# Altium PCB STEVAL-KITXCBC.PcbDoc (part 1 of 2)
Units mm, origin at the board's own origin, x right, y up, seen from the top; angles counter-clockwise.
Board outline 110 x 100 mm, 4 copper layers (Top Layer, Ground Layer, Power Layer, Bottom Layer), stack 1.572 mm thick; 141 components, 96 nets, 501 pads, 315 vias.
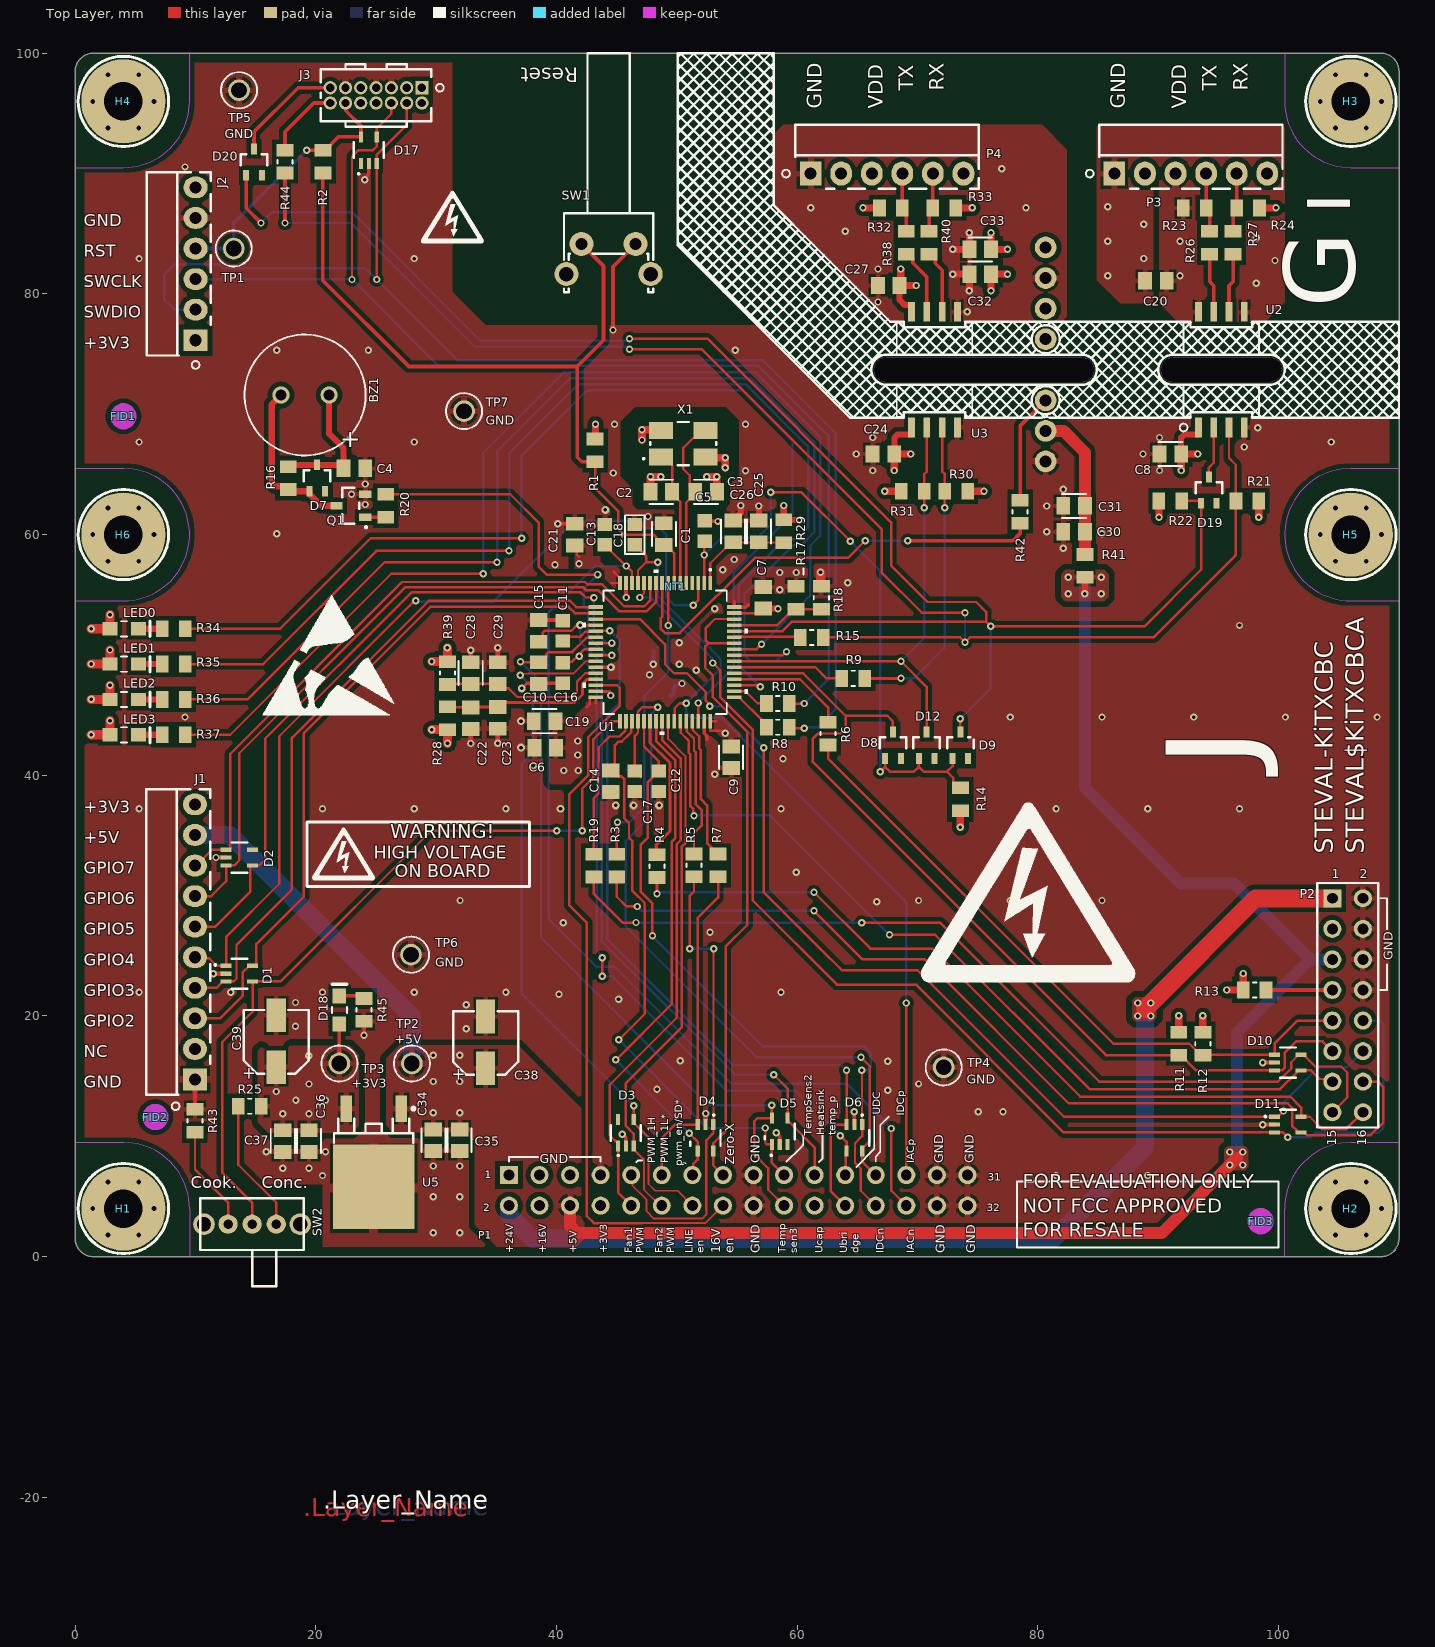
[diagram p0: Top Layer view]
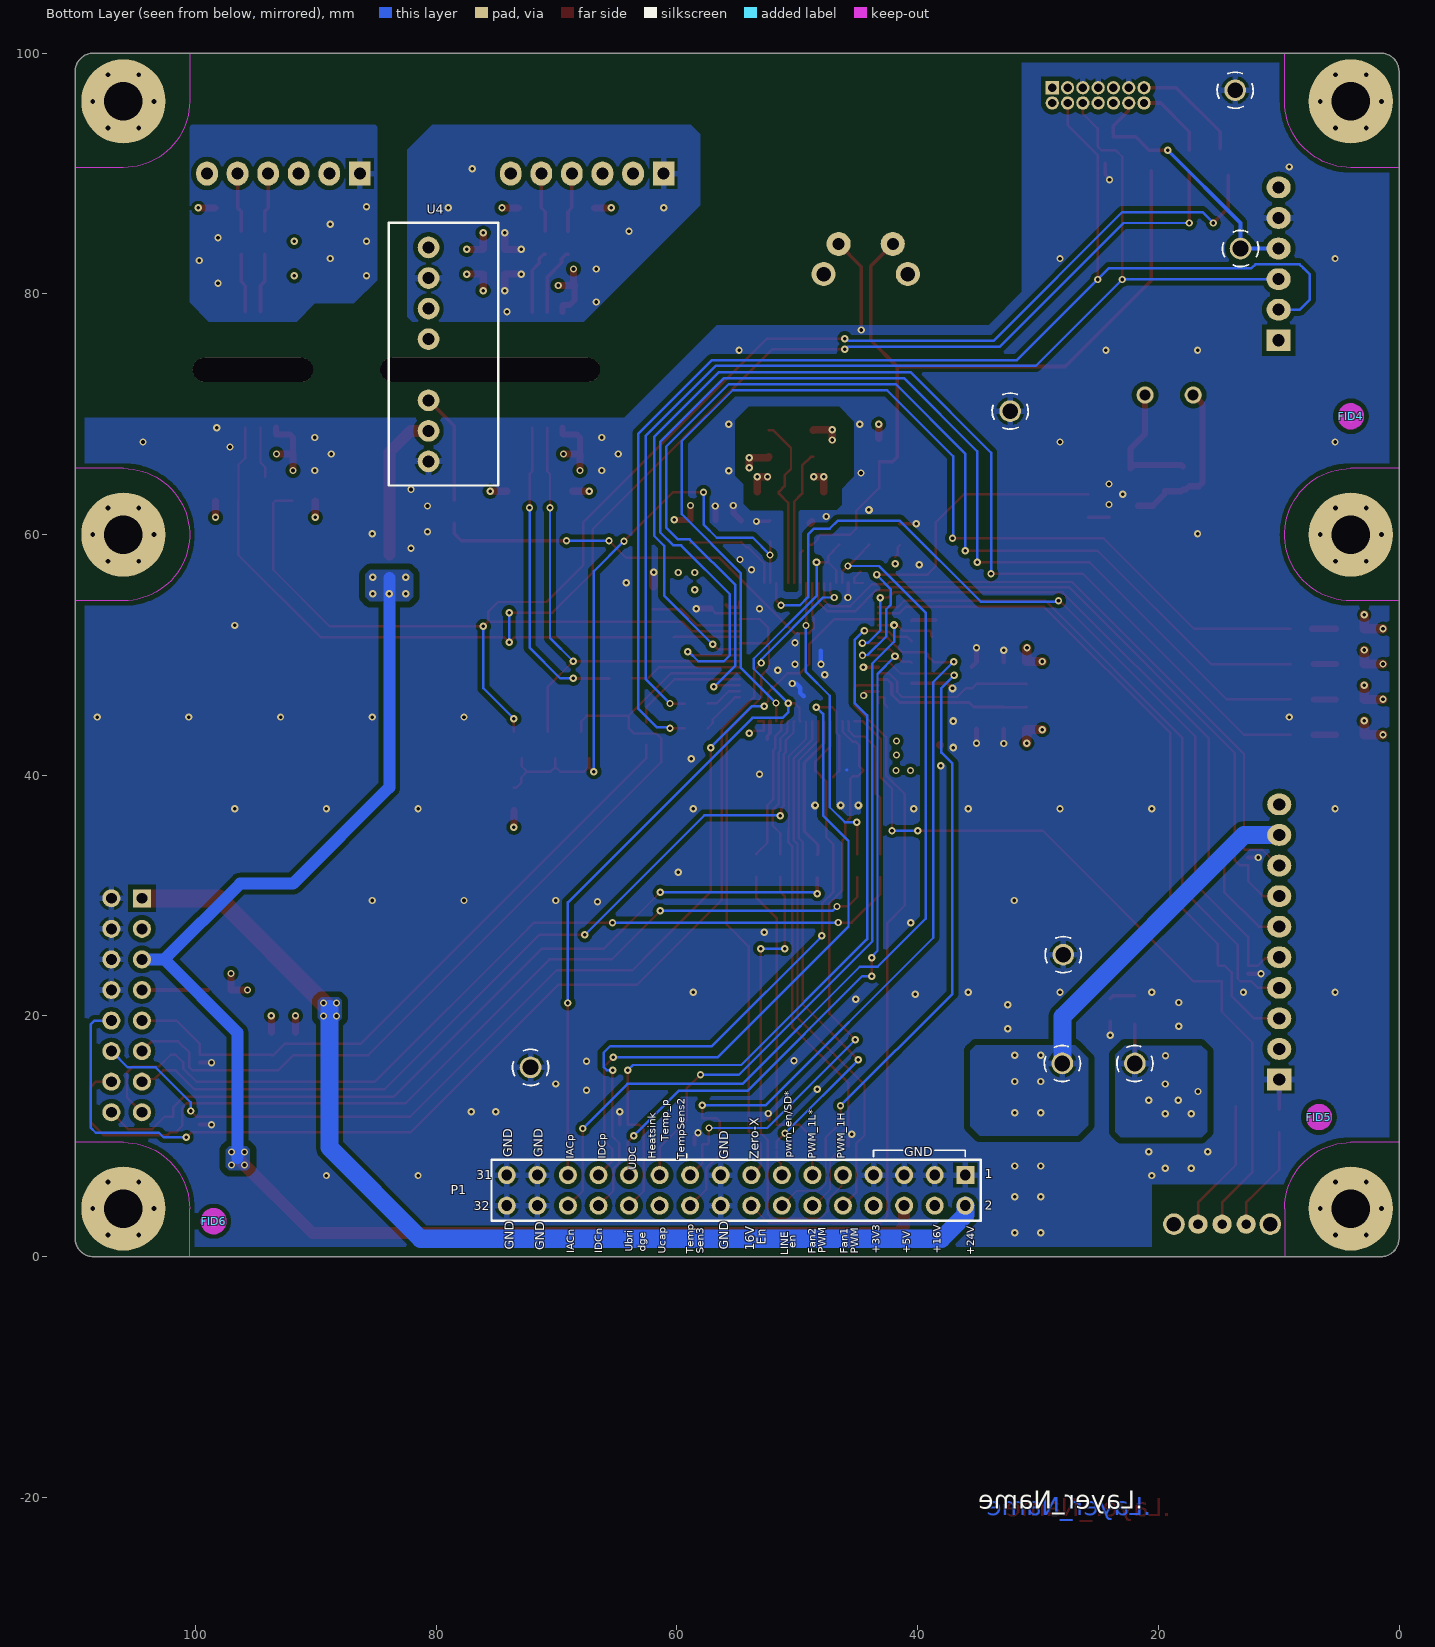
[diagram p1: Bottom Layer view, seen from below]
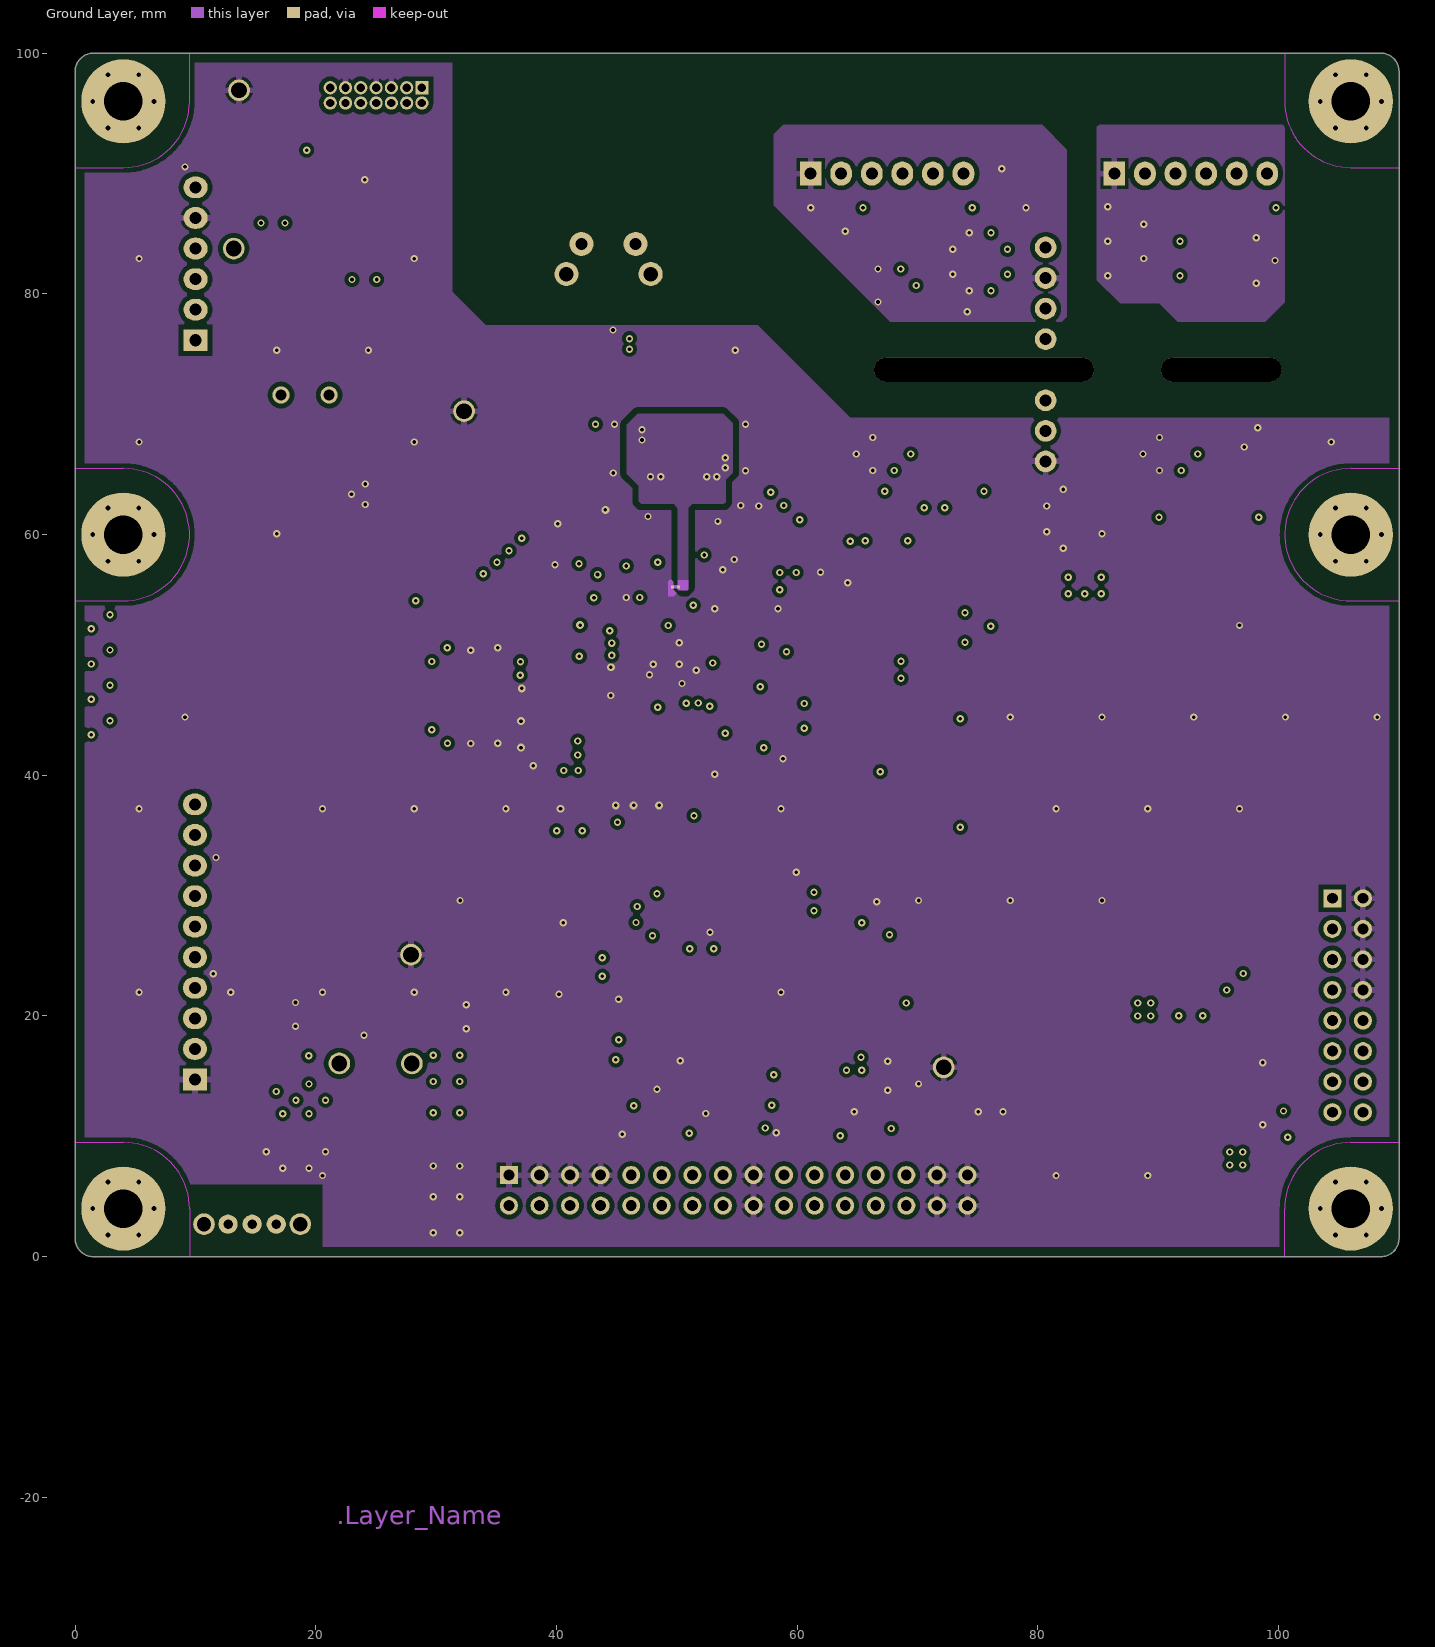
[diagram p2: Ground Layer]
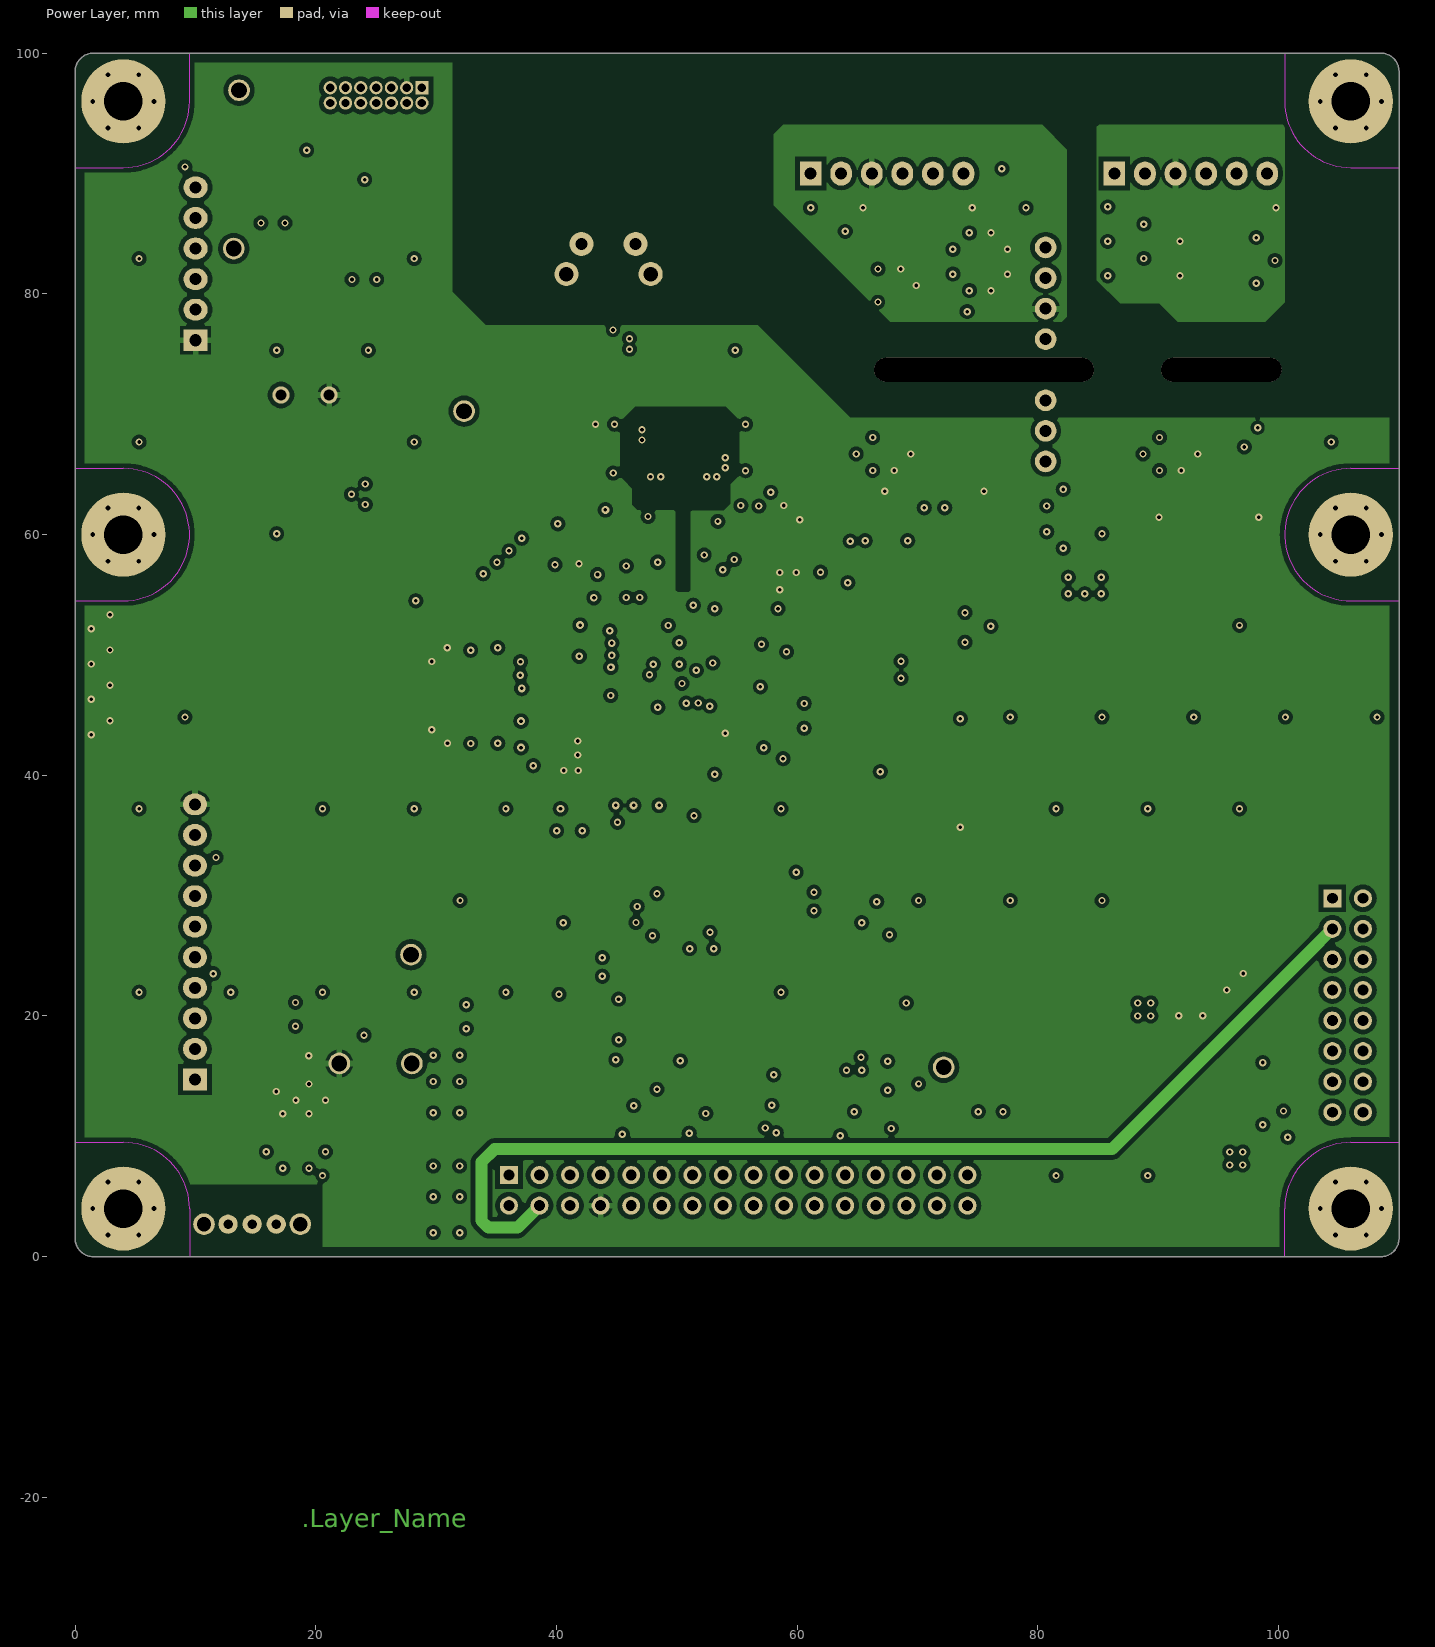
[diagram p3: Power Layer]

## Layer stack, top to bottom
Top Solder: solder mask 0.0127, Solder Resist, Dk 3.5
Top Layer: signal copper 0.0356
Dielectric1: prepreg 0.36, FR-4 High TG, Dk 4.2
Ground Layer: signal copper 0.0356
Dielectric 2: core 0.71, FR-4 High TG, Dk 4.2
Power Layer: signal copper 0.0356
Dielectric 3: prepreg 0.36, FR-4 High TG, Dk 4.2
Bottom Layer: signal copper 0.0356
Bottom Solder: solder mask 0.0127, Solder Resist, Dk 3.5

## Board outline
1.5,0 cw(c1.5,1.5) 0,1.5 0,98.5 cw(c1.5,98.5) 1.5,100 108.5,100 cw(c108.5,98.5) 110,98.5 110,1.5 cw(c108.5,1.5) 108.5,0

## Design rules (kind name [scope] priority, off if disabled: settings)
AcuteAngle [All] p1: minimum=4.50000000000000E+0001 checktracksonly=FALSE
AssemblyTestPointUsage [All] p1: valid=2
BoardOutlineClearance BoardOutlineClearance_MountingHoles [OnCopper and InComponentClass('Mounting Holes')] p1: gap=1.016 ignorepadtopadclearanceinfootprint=FALSE
BoardOutlineClearance BoardOutlineClearance_Poly [OnCopper and IsPoly] p2: gap=0.8 ignorepadtopadclearanceinfootprint=FALSE
BoardOutlineClearance [OnCopper and Not InComponentClass('Logo') and not InComponentClass('FiducialMark') and not InRegion(1000,500,4000,800) and not InPoly] p3: gap=0.737 ignorepadtopadclearanceinfootprint=FALSE except(0.635: SMDPad-OutlineEdge THPad-OutlineEdge)
Clearance Clearance_Keepouts [((IsTrack Or IsArc) And Not InPoly) And IsFree and IsKeepOut vs ((IsTrack Or IsArc) And Not InPoly) And IsFree and IsKeepOut] p1: gap=0 ignorepadtopadclearanceinfootprint=FALSE
Clearance Clearance_Poly [InPolygon] p2: gap=0.254 ignorepadtopadclearanceinfootprint=TRUE except(0.305: Via-Poly; 0.381: Arc-Poly Track-Poly SMDPad-Poly THPad-Poly Fill-Poly; 0.508: Poly-Poly)
Clearance Clearance_FiducialMark [IsKeepOut and InComponentClass('FiducialMark') vs IsPad and InComponentClass('FiducialMark')] p3: gap=0 ignorepadtopadclearanceinfootprint=FALSE
Clearance [All] p4: gap=0.229 ignorepadtopadclearanceinfootprint=TRUE except(0: Arc-SMDPad; 0.193: Track-SMDPad SMDPad-SMDPad; 0.508: Poly-Poly)
ComponentClearance ComponentClearance_MountingHoles_FiducialMarks [InComponentClass('Mounting Holes') vs InComponentClass('FiducialMark')] p1: gap=1.27 collisioncheckmode=3 verticalgap=0.254 showdistances=FALSE
ComponentClearance ComponentClearance_Shunt [InComponentClass('Header') vs InComponentClass('Shunt')] p2: gap=0 collisioncheckmode=3 verticalgap=0 showdistances=FALSE
ComponentClearance ComponentClearance_Logo [InComponentClass('Logo')] p3: gap=1.016 collisioncheckmode=3 verticalgap=0.254 showdistances=FALSE
ComponentClearance ComponentClearance_ScrewToNut [(HasFootprint('NY PMS 440 0025 PH')) vs (HasFootprint('Keystone_1902C'))] p4: gap=0.127 collisioncheckmode=3 verticalgap=0.254 showdistances=FALSE
ComponentClearance ComponentClearance_MountingHoles [InComponentClass('Mounting Holes')] p5: gap=6.35 collisioncheckmode=3 verticalgap=2540 showdistances=FALSE
ComponentClearance ComponentClearance_SmallPassives [HasFootprint('0201*') or HasFootprint('0402*') or HasFootprint('0508') or HasFootprint('0603*') or HasFootprint('0612') or HasFootprint('0805*') or HasFootprint('0815*') or HasFootprint('0830*') or HasFootprint('1206*') or HasFootprint('1210*') or HasFootprint('1808*') or HasFootprint('1812*') or HasFootprint('1825*') or HasFootprint('2010*') or HasFootprint('2220*') or HasFootprint('2225*') or HasFootprint('2512*') or HasFootprint('2728*') or HasFootprint('3518*') vs HasFootprint('0201*') or HasFootprint('0402*') or HasFootprint('0508') or HasFootprint('0603*') or HasFootprint('0612') or HasFootprint('0805*') or HasFootprint('0815*') or HasFootprint('0830*') or HasFootprint('1206*') or HasFootprint('1210*') or HasFootprint('1808*') or HasFootprint('1812*') or HasFootprint('1825*') or HasFootprint('2010*') or HasFootprint('2220*') or HasFootprint('2225*') or HasFootprint('2512*') or HasFootprint('2728*') or HasFootprint('3518*')] p6: gap=0.38 collisioncheckmode=3 verticalgap=0.254 showdistances=FALSE
ComponentClearance ComponentClearance_THtoSMT [IsThruComponent vs IsSMTComponent] p7: gap=0.762 collisioncheckmode=3 verticalgap=0.635 showdistances=FALSE
ComponentClearance ComponentClearance_THtoTH [IsThruComponent vs IsThruComponent] p8: gap=0.762 collisioncheckmode=3 verticalgap=0.635 showdistances=FALSE
ComponentClearance [All] p9: gap=0.635 collisioncheckmode=3 verticalgap=0.254 showdistances=FALSE
DiffPairsRouting [All] p1: maxlimit=2.54 minlimit=0.254 mostfreqgap=0.254 toplayer_minwidth=0.381 toplayer_maxwidth=0.381 toplayer_prefwidth=0.381 midlayer1_minwidth=0.381 midlayer1_maxwidth=0.381 midlayer1_prefwidth=0.381 midlayer2_minwidth=0.381 midlayer2_maxwidth=0.381 midlayer2_prefwidth=0.381 bottomlayer_minwidth=0.381 bottomlayer_maxwidth=0.381 bottomlayer_prefwidth=0.381 maxuncoupledlength=25.4
FabricationTestPointUsage TestPointUsage [All] p1: valid=2 allowmultiple=FALSE
FabricationTestpoint Testpoint [All] p1: side=3 testpointundercomponent=TRUE minsize=1.016 maxsize=2.54 preferedsize=1.524 minholesize=0 maxholesize=1.016 preferedholesize=0.813 testpointgrid=0.025 allowsidetop=TRUE allowsidebottom=TRUE usegrid=TRUE gridtolerance=0
FanoutControl Fanout_LCC [IsLCC] p1: bgadir=Out bgaviamode=Centered fanoutstyle=Auto fanoutdirection=Alternating viagrid=0.025 // Fanout_LCC (Default Rule)
FanoutControl Fanout_BGA [IsBGA] p2: bgadir=Out bgaviamode=Centered fanoutstyle=Auto fanoutdirection=Alternating viagrid=0.025 // Fanout_BGA (Default Rule)
FanoutControl Fanout_Default [All] p4: bgadir=Out bgaviamode=Centered fanoutstyle=Auto fanoutdirection=Alternating viagrid=0.025 // Fanout_Default (Default Rule)
FanoutControl Fanout_Small [(CompPinCount < 5)] p5: bgadir=Out bgaviamode=Centered fanoutstyle=Auto fanoutdirection=OutThenIn viagrid=0.025 // Fanout_Small (Default Rule)
HoleSize [All] p1: absolutevalues=TRUE maxlimit=10 minlimit=0.2 maxpercent=80.000 minpercent=20.000
HoleToHoleClearance [All] p1: gap=0.2 allowstackedmicrovias=TRUE
MinimumAnnularRing MinimumAnnularRing_ThermalPadVias [IsVia and InAnyComponent] p1: minimumring=0.15
MinimumAnnularRing [All] p2: minimumring=0.127
MinimumSolderMaskSliver MinimumSolderMaskSliver_Logo [InComponentClass('Logo') vs InComponentClass('Logo')] p1: minsoldermaskwidth=0.018
MinimumSolderMaskSliver [All] p2: minsoldermaskwidth=0.01
PlaneConnect [All] p1: planeconnectstyle=Relief reliefexpansion=0.254 reliefentries=4 reliefconductorwidth=0.254 reliefairgap=0.254
PolygonConnect [All] p1: thpad.connectstyle=Relief thpad.reliefconductorwidth=0.508 thpad.reliefentries=4 thpad.polygonreliefangle="90 Angle" thpad.airgapwidth=0.254 smdpad.connectstyle=Relief smdpad.reliefconductorwidth=0.4 smdpad.reliefentries=4 smdpad.polygonreliefangle="90 Angle" smdpad.airgapwidth=0.2 via.connectstyle=Direct via.reliefconductorwidth=0.254 via.reliefentries=4 via.polygonreliefangle="90 Angle" via.airgapwidth=0.254
RoutingVias ThermalPadVias [IsVia and InAnyComponent] p1: holewidth=0.2 width=0.5 viastyle="Through Hole" minholewidth=0.2 minwidth=0.5 maxholewidth=0.33 maxwidth=0.6
RoutingVias [All] p2: holewidth=0.305 width=0.61 viastyle="Through Hole" minholewidth=0.3 minwidth=0.6 maxholewidth=0.31 maxwidth=0.62
SilkToBoardRegionClearance [Not ((IsComment or IsDesignator) And (Hide <> 'False')) and not InRegion(1000,500,4000,800)] p1:
SilkToSilkClearance SilkToSilkClearance_Pb-FreeLogo [(HasFootprint('Pb-Free_Overlay_Medium') OR HasFootprint('Pb-Free_Overlay_Small')) vs (HasFootprint('Pb-Free_Overlay_Medium') OR HasFootprint('Pb-Free_Overlay_Small'))] p1: silktosilkclearance=0
SilkToSilkClearance [All] p2: silktosilkclearance=0.013
SilkToSolderMaskClearance SilkToComponentPadClearance [(IsPad or IsFill or IsRegion) and InAnycomponent] p1: minsilkscreentomaskgap=0.01 clearancetoexposedcopper=FALSE
SilkToSolderMaskClearance "Silk to Solder Mask Opening" [All] p2: minsilkscreentomaskgap=0 clearancetoexposedcopper=FALSE
SolderMaskExpansion [All] p1: expansion=0.1 istentingtop=FALSE
UnRoutedNet [All] p1: checkbadconnections=TRUE
Width [All] p1: maxlimit=2.54 minlimit=0.152 preferedwidth=0.254 minimp=50.000000 maximp=50.000000 favimp=50.000000 checkconnectedcopper=TRUE
13 further rules are at their usual default settings.

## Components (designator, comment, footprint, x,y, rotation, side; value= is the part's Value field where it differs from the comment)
BZ1 "ABI-050-RC" TR_MP-ABI-050-RC_MTC 21.1,71.6 r180 top
C1 "100n" CC0805 48.916,60.046 r90 top locked
C2 "22p" CC0805 48.694,63.554 r0 top locked
C3 "22p" CC0805 52.425,63.554 r0 top locked
C4 "100n" CC0805 23.2,65.5 r0 top
C5 "1nF" CC0603 52.3,60.3 r90 top
C6 "10u" CC0805 39.05,42.3 r180 top
C7 "100n" CC0805 57.179,54.747 r270 top
C8 "100n" CC0805 91,66.7 r180 top locked
C9 "100n" CC0805 54.5,41.5 r270 top
C10 "100nF" CC0805 38.5,48.5 r270 top
C11 "1nF" CC0603 40.5,52 r90 top
C12 "1nF" CC0603 48.5,39.5 r270 top
C13 "1nF" CC0603 44,60 r90 top
C14 "100nF" CC0805 44.5,39.5 r270 top
C15 "100nF" CC0805 38.5,52 r90 top
C16 "1nF" CC0603 40.5,48.5 r270 top
C17 "1nF" CC0603 46.5,39.5 r270 top
C18 "1nF" CC0603 46.5,60 r90 top
C19 "100n" CC0805 39,44.5 r180 top
C20 "10n" CC0805 89.8,81.1 r180 top
C21 "100n" CC0805 41.5,60 r90 top
C22 "10u" CC0805 32.857,44.747 r270 top
C23 "100n" CC0805 35.107,44.762 r270 top
C24 "100n" CC0805 67.16,66.7 r180 top
C25 "10u" CC0805 56.808,60.271 r90 top locked
C26 "100n" CC0805 54.666,60.271 r90 top locked
C27 "10n" CC0805 67.6,80.7 r180 top
C28 "10u" CC0805 32.857,48.5 r90 top locked
C29 "100n" CC0805 35.107,48.5 r90 top
C30 "10u" CC0805 83,60.234 r180 top
C31 "100n" CC0805 83,62.384 r180 top
C32 "10u" CC0805 75.2,81.645 r180 top
C33 "100n" CC0805 75.2,83.7 r180 top
C34 "100n" CC0805 29.761,9.677 r270 top locked
C35 "10u" CC0805 31.941,9.677 r270 top locked
C36 "10u" CC0805 19.423,9.606 r270 top locked
C37 "100n" CC0805 17.252,9.606 r270 top locked
C38 "47u" "ELCAP SMD D5H5.8P1.5" 34.1,17.8 r0 top value=47uF
C39 "47u" "ELCAP SMD D5H5.8P1.5" 16.7,17.9 r0 top value=47uF
D1 "ESDALC6V1W5" SOT323_5 13.633,23.518 r270 top
D2 "ESDALC6V1W5" SOT323_5 13.633,33.164 r270 top
D3 "ESDALC6V1W5" SOT323_5 45.758,10.294 r0 top
D4 "ESDALC6V1W5" SOT323_5 52.371,9.87 r180 top
D5 "ESDALC6V1W5" SOT323_5 58.542,10.416 r0 top
D6 "ESDALC6V1W5" SOT323_5 64.742,9.87 r180 top
D7 "BAT54WFILM" SOT323 20.1,64.7 r0 top
D8 "BAT54WFILM" SOT323 67.95,42.5 r0 top
D9 "BAT54WFILM" SOT323 73.55,42.5 r0 top
D10 "ESDALC6V1W5" SOT323_5 100.762,16.129 r270 top
D11 "ESDALC6V1W5" SOT323_5 100.762,10.973 r270 top
D12 "BAT54WFILM" SOT323 70.75,42.5 r0 top
D17 "ESDALC6V1W5" SOT323_5 24.4,91.95 r0 top
D18 "KPT-2012SGC" LED_KPT-2012EC 21.948,20.5 r270 top
D19 "BAT54WFILM" SOT323 94.2,63.7 r0 top
D20 "BAT54WFILM" SOT323 14.854,90.956 r0 top
FID1 "Fiducial" Fiducial10-20 4,69.832 r0 top
FID2 "Fiducial" Fiducial10-20 6.655,11.6 r0 top
FID3 "Fiducial" Fiducial10-20 98.501,2.946 r0 top
FID4 "Fiducial" Fiducial10-20 4,69.832 r180 bottom
FID5 "Fiducial" Fiducial10-20 6.655,11.6 r180 bottom
FID6 "Fiducial" Fiducial10-20 98.501,2.946 r180 bottom
H1 "Hole" "HOLE_M3 - D8" 4,4 r0 top net-tie
H2 "Hole" "HOLE_M3 - D8" 106,4 r0 top net-tie
H3 "Hole" "HOLE_M3 - D8" 106,96 r0 top net-tie
H4 "Hole" "HOLE_M3 - D8" 4,96 r0 top net-tie
H5 "Hole" "HOLE_M3 - D8" 106,60 r0 top net-tie
H6 "Hole" "HOLE_M3 - D8" 4,60 r0 top net-tie
J1 "TSW-110-08-G-S-RA" "SIP10 - Male - RA" 9.95,26.15 r90 top
J2 "TSW-106-08-G-S-RA" "SIP6 - MALE - RA" 10,82.5 r90 top
J3 "FTSH-107-01-F-D-K" SAMTEC-FTSH-107-01-X-D-K 25,96.5 r180 top
LED0 "KPT-2012EC" LED_KPT-2012EC 4.069,52.178 r180 top
LED1 "KPT-2012SGC" LED_KPT-2012EC 4.069,49.242 r180 top
LED2 "APT2012YC" LED_KPT-2012EC 4.069,46.305 r180 top
LED3 "APTD2012LQBC/D" LED_KPT-2012EC 4.069,43.369 r180 top
NT1 "Net-Tie" Net-Tie_10mil 49.886,55.652 r180 top locked net-tie
P1 "SSW-116-01-G-D" HDR2X16 36.04,6.78 r0 bottom locked
P2 "TSW-108-07-G-D" HDR2X8 104.46,29.78 r270 top locked
P3 "TSW-106-08-G-S-RA" "SIP6 - MALE - RA" 92.7,90 r0 top
P4 "TSW-106-08-G-S-RA" "SIP6 - Male - RA" 67.46,90 r0 top
Q1 "2STR1160" SOT23_3 22.9,62.4 r90 top
R1 "10K" RC0805 43.2,67 r270 top
R2 "220R" RC0805 20.6,91 r90 top
R3 "100R" RC0805 45,32.5 r270 top
R4 "100R" RC0805 48.342,32.457 r270 top locked
R5 "100R" RC0805 51.416,32.507 r270 top locked
R6 "100R" RC0805 62.557,43.472 r270 top locked
R7 "100R" RC0805 53.421,32.507 r270 top
R8 "4R7" RC0805 58.394,43.997 r180 top locked
R9 "100R" RC0805 64.653,48.057 r0 top locked
R10 "4R7" RC0805 58.394,45.974 r180 top locked
R11 "1k" RC0805 91.7,17.7 r90 top
R12 "1k" RC0805 93.7,17.7 r90 top
R13 "NM" RC0805 98,22.16 r0 top
R14 "1k" RC0805 73.55,38 r270 top
R15 "100R" RC0805 61.206,51.455 r180 top locked
R16 "NM" RC0805 17.7,64.7 r90 top
R17 "NM" RC0805 59.9,54.747 r90 top
R18 "10k" RC0805 61.998,54.747 r90 top locked
R19 "100R" RC0805 43.1,32.5 r270 top
R20 "10k" RC0805 25.8,62.4 r90 top
R21 "1k" RC0805 97.4,62.8 r0 top
R22 "1k" RC0805 91,62.8 r180 top
R23 "1k" RC0805 93.02,87.147 r180 top
R24 "1k" RC0805 97.46,87.147 r0 top
R25 "10k" RC0805 14.5,12.5 r0 top
R26 "22R" RC0805 94.266,84.254 r90 top
R27 "22R" RC0805 96.214,84.254 r90 top
R28 "0R" RC0805 30.933,44.747 r90 top
R29 "0R" RC0805 58.878,60.271 r270 top
R30 "1k" RC0805 73.2,63.6 r0 top
R31 "1k" RC0805 69.6,63.6 r180 top
R32 "1k" RC0805 67.78,87.15 r180 top
R33 "1k" RC0805 72.22,87.15 r0 top
R34 "330R" RC0805 8.186,52.178 r0 top
R35 "330R" RC0805 8.186,49.242 r0 top
R36 "330R" RC0805 8.186,46.306 r0 top
R37 "330R" RC0805 8.186,43.369 r0 top
R38 "22R" RC0805 69.05,84.25 r90 top
R39 "0R" RC0805 30.933,48.5 r270 top locked
R40 "22R" RC0805 70.95,84.25 r90 top
R41 "0R" RC0805 83.9,57.4 r270 top
R42 "22" RC0805 78.512,61.907 r270 top
R43 "10k" RC0805 9.95,11.287 r90 top
R44 "22R" RC0805 17.43,91 r270 top
R45 "330R" RC0805 24,20.5 r270 top
SW1 "Reset" "PUSH  BUTTON SPST SIDE TH - LONG" 44.315,83.65 r180 top value=SKHHNKA010
SW2 "Slide switch" "SLIDE SWITCH SPDT RA" 14.7,2.7 r180 top
TP1 "ResetDSP" TP_20-2136 13.17,83.77 r0 top value="Test Point"
TP2 "5V" TP_20-313142 27.973,16.053 r90 top value="Test Point"
TP3 "3v3" TP_20-313142 21.948,16.053 r90 top value="Test Point"
TP4 "GND" TP_20-313142 72.164,15.728 r0 top value="Test Point"
TP5 "GND" TP_20-313142 13.612,96.926 r0 top value="Test Point"
TP6 "GND" TP_20-313142 27.9,25.094 r0 top value="Test Point"
TP7 "GND" TP_20-313142 32.309,70.261 r0 top value="Test Point"
U1 "STM32G474RET6" LQFP64-10x10mm 49.014,50.229 r270 top locked
U2 "STISO621W" SO_SO621W_STM 95.24,73.7 r90 top
U3 "STISO621W" SO_SO621W_STM 71.4,73.7 r90 top
U4 "TMR 3-0511" "VOLTAGE REGULATOR ISO SIP 8" 80.642,73.7 r90 bottom
U5 "LF33CDT-TR" "TO-252 DPAK" 24.8,7.9 r180 top
X1 "8MHz" CRYSTAL_RESONATOR_SMD_5x3.2 50.525,67.56 r0 top value=Frequency

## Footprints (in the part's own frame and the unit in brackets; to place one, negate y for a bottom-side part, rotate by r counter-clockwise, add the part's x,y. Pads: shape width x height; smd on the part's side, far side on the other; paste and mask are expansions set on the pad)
CC0603 [mm]
  rect 1.1x1.2 smd paste+0: 1(-0.85,0) 2(0.85,0)
  body extent -0.8,-0.4 0.8,0.4, height 0.95
CC0805 [mm]
  rect 1.15x1.45 smd: 1(-0.9,0) 2(0.9,0)
  silkscreen extent -1,-1 1,1, body extent -1,-0.63 1,0.63, height 1.45
CRYSTAL_RESONATOR_SMD_5x3.2 [mm]
  rect 2x1.4 smd: 1(-1.85,-1.1) 2(-1.85,1.1) 2(1.85,-1.1) 3(1.85,1.1)
  silkscreen extent -3.35,-1.8 2.75,1.8, body extent -2.5,-1.6 2.5,1.6, height 1
"ELCAP SMD D5H5.8P1.5" [mm]
  rect 1.6x2.8 smd: 1(0,-2.15) 2(0,2.15)
  silkscreen extent -2.7,-2.7 2.7,2.6, body extent -2.65,-3 2.65,3, height 5.8
Fiducial10-20 [mm]
  round 1 smd mask+0.5: 1(0,0)
  Top Layer keep-out circle w1.178: c0,0 r0.5
HDR2X8 [mm] "Connector; Header; 8x2 Position"
  rect 1.5x1.5 hole 0.9: 1(0,0)
  round 1.5 hole 0.9: 2(0,2.54) 3(2.54,0) 4(2.54,2.54) 5(5.08,0) 6(5.08,2.54) 7(7.62,0) 8(7.62,2.54) 9(10.16,0) 10(10.16,2.54) 11(12.7,0) 12(12.7,2.54) 13(15.24,0) 14(15.24,2.54) 15(17.78,0) 16(17.78,2.54)
  silkscreen extent -1.27,-1.27 19.05,3.81
HDR2X16 [mm] "Connector; Header; 16x2 Position"
  rect 1.5x1.5 hole 0.9: 1(0,0)
  round 1.5 hole 0.9: 2(0,2.54) 3(2.54,0) 4(2.54,2.54) 5(5.08,0) 6(5.08,2.54) 7(7.62,0) 8(7.62,2.54) 9(10.16,0) 10(10.16,2.54) 11(12.7,0) 12(12.7,2.54) 13(15.24,0) 14(15.24,2.54) 15(17.78,0) 16(17.78,2.54) 17(20.32,0) 18(20.32,2.54) 19(22.86,0) 20(22.86,2.54) 21(25.4,0) 22(25.4,2.54) 23(27.94,0) 24(27.94,2.54) 25(30.48,0) 26(30.48,2.54) 27(33.02,0) 28(33.02,2.54) 29(35.56,0) 30(35.56,2.54) 31(38.1,0) 32(38.1,2.54)
  silkscreen extent -1.27,-1.27 39.37,3.81
"HOLE_M3 - D8" [mm]
  round 0.8 hole 0.4 mask+0: 1(-2.55,0) 1(-1.275,-2.208) 1(-1.275,2.208) 1(1.275,-2.208) 1(1.275,2.208) 1(2.55,0)
  round 7 hole 3.2 mask+0.1: 1(0,0)
  silkscreen extent -3.75,-3.75 3.75,3.75
LED_KPT-2012EC [mm] "LED, 2.00 MM X 1.25 MM, SMD-2P"
  rect 1.25x1.1 smd paste+0: 1(-1.175,0) 2(1.175,0)
  silkscreen extent -2.14,-0.62 0.25,0.65, body extent -1,-0.63 1,0.63, height 0.75
LQFP64-10x10mm [mm]
  rect 1.194x0.305 smd paste+0 mask+0: 1(-5.75,3.75) 2(-5.75,3.25) 3(-5.75,2.75) 4(-5.75,2.25) 5(-5.75,1.75) 6(-5.75,1.25) 7(-5.75,0.75) 8(-5.75,0.25) 9(-5.75,-0.25) 10(-5.75,-0.75) 11(-5.75,-1.25) 12(-5.75,-1.75) 13(-5.75,-2.25) 14(-5.75,-2.75) 15(-5.75,-3.25) 16(-5.75,-3.75) 33(5.75,-3.75) 34(5.75,-3.25) 35(5.75,-2.75) 36(5.75,-2.25) 37(5.75,-1.75) 38(5.75,-1.25) 39(5.75,-0.75) 40(5.75,-0.25) 41(5.75,0.25) 42(5.75,0.75) 43(5.75,1.25) 44(5.75,1.75) 45(5.75,2.25) 46(5.75,2.75) 47(5.75,3.25) 48(5.75,3.75)
  rect 0.305x1.194 smd paste+0 mask+0: 17(-3.75,-5.75) 18(-3.25,-5.75) 19(-2.75,-5.75) 20(-2.25,-5.75) 21(-1.75,-5.75) 22(-1.25,-5.75) 23(-0.75,-5.75) 24(-0.25,-5.75) 25(0.25,-5.75) 26(0.75,-5.75) 27(1.25,-5.75) 28(1.75,-5.75) 29(2.25,-5.75) 30(2.75,-5.75) 31(3.25,-5.75) 32(3.75,-5.75) 49(3.75,5.75) 50(3.25,5.75) 51(2.75,5.75) 52(2.25,5.75) 53(1.75,5.75) 54(1.25,5.75) 55(0.75,5.75) 56(0.25,5.75) 57(-0.25,5.75) 58(-0.75,5.75) 59(-1.25,5.75) 60(-1.75,5.75) 61(-2.25,5.75) 62(-2.75,5.75) 63(-3.25,5.75) 64(-3.75,5.75)
  silkscreen extent -6.93,-6.85 6.85,6.85, body extent -6,-6 6,6, height 1.6
Net-Tie_10mil [mil] "10mil net tie, no solder mask opening, no solder paste"
  rect 10x10 on Mid1 paste-5 mask-5: 1(-10,0) 2(10,0)
  Ground Layer region: -6,-5 6,-5 6,5 -6,5
"PUSH  BUTTON SPST SIDE TH - LONG" [mm]
  round 2 hole 1.2: 1(-3.5,2) 4(3.5,2)
  round 2 hole 1: 2(-2.25,-0.5) 3(2.25,-0.5)
  silkscreen extent -3.7,-16.35 3.7,3.5, body extent -4.25,-16.33 4.25,3.57, height 7.4
RC0805 [mm]
  rect 1.05x1.4 smd: 1(-0.95,0) 2(0.95,0)
  body extent -1,-0.63 1,0.63, height 0.84
SAMTEC-FTSH-107-01-X-D-K [mm]
  rect 1.1x1.1 hole 0.7 mask+0.05: 1(-3.81,-0.635)
  round 1.1 hole 0.7 mask+0.05: 2(-3.81,0.635) 3(-2.54,-0.635) 4(-2.54,0.635) 5(-1.27,-0.635) 6(-1.27,0.635) 7(0,-0.635) 8(0,0.635) 9(1.27,-0.635) 10(1.27,0.635) 11(2.54,-0.635) 12(2.54,0.635) 13(3.81,-0.635) 14(3.81,0.635)
  silkscreen extent -4.6,-2.6 4.6,2.6, body extent -4.44,-2.54 4.45,2.54, height 5.71
"SIP6 - MALE - RA" [mm]
  rect 1.8x2 hole 1: 1(-6.35,0)
  oval 1.8x2 hole 1: 2(-3.81,0) 3(-1.27,0) 4(1.27,0) 5(3.81,0) 6(6.35,0)
  silkscreen extent -7.62,-1.27 7.62,4.06, body extent -7.62,-0.3 7.62,9.92, height 3.07
"SIP6 - Male - RA" [mm]
  rect 1.8x2 hole 1: 1(-6.35,0)
  oval 1.8x2 hole 1: 2(-3.81,0) 3(-1.27,0) 4(1.27,0) 5(3.81,0) 6(6.35,0)
  silkscreen extent -7.62,-1.27 7.62,4.06, body extent -7.62,-0.3 7.62,9.92, height 3.07
"SIP10 - Male - RA" [mm]
  rect 1.8x2 hole 1: 1(-11.43,0)
  oval 1.8x2 hole 1: 2(-8.89,0) 3(-6.35,0) 4(-3.81,0) 5(-1.27,0) 6(1.27,0) 7(3.81,0) 8(6.35,0) 9(8.89,0) 10(11.43,0)
  silkscreen extent -12.7,-1.27 12.7,4.06, body extent -12.7,-0.3 12.7,9.92, height 3.07
"SLIDE SWITCH SPDT RA" [mm]
  round 1.6 hole 0.8 mask+0.102: 1(2,0) 2(0,0) 3(-2,0)
  round 1.8 hole 1.2 mask+0.102: ""(-4,0) ""(4,0)
  silkscreen extent -4.3,-2.15 4.3,5.15, body extent -4.59,-2.15 4.59,5.15, height 3.5
SO_SO621W_STM [mil]
  rect 64x22 smd paste+0 mask+0: 1(-189,75) 2(-189,25) 3(-189,-25) 4(-189,-75) 5(189,-75) 6(189,-25) 7(189,25) 8(189,75)
  silkscreen extent -154,-123 155,124, body extent -207,-119 207,119, height 104
SOT23_3 [mm] "SOT23, 3-Leads, Body 3.04x1.4mm, Pitch 0.95mm, IPC Medium Density"
  rect 0.6x1 smd: 1(-0.95,-1.2) 2(0.95,-1.2) 3(0,1.2)
  silkscreen extent -1.84,-1.32 1.5,0.7, body extent -1.46,-1.26 1.46,1.26, height 0.96
SOT323 [mm] "SOT323, 3-Leads, Body 2,00x2,10mm, Pitch 0,65mm, IPC Medium Density"
  rect 0.5x0.9 smd: 1(-0.65,-1.1) 2(0.65,-1.1) 3(0,1.1)
  silkscreen extent -1.1,-0.25 1.1,0.65, body extent -1.05,-1.15 1.05,1.15, height 1
SOT323_5 [mm] "SOT323, 5-Leads, Body 2,00x2,10mm, Pitch 0,65mm, IPC Medium Density"
  rect 0.35x0.9 smd mask+0: 1(-0.65,-1.1) 2(0,-1.1) 3(0.65,-1.1) 4(0.65,1.1) 5(-0.65,1.1)
  silkscreen extent -1.25,-2.05 1.25,0.65, body extent -1.05,-1.05 1.05,1.05, height 1
"TO-252 DPAK" [mm] "D-PAK, 3-Pads, Body 8,15x6,66mm (max), IPC Medium Density"
  rect 0.95x2.2 smd: 1(-2.28,-4.4) 3(2.28,-4.4)
  rect 6.8x7 smd: 2(0,2.1)
  silkscreen extent -3.43,-4.52 3.3,-1.55, body extent -3.27,-4.81 3.27,5.13, height 2.39
TP_20-2136 [mm] "TEST POINT, BLACK, TH"
  round 1.8 hole 1.3: 1(0,0)
  silkscreen extent -1.5,-1.5 1.5,1.5, body extent -1.49,-1.5 1.5,1.5, height 5.4
TP_20-313142 [mm] "TEST POINT, GREEN,  TH"
  round 1.8 hole 1.3: 1(0,0)
  silkscreen extent -1.5,-1.5 1.5,1.5, body extent -1.49,-1.5 1.5,1.5, height 5.4
TR_MP-ABI-050-RC_MTC [mil]
  round 56 hole 36 mask+0: 1(0,0) 2(157.48,0)
  silkscreen extent -119,-198 277,198, body extent -114,-193 272,193, height 198
"VOLTAGE REGULATOR ISO SIP 8" [mm]
  round 1.8 hole 1: 1(-7.62,0) 2(-5.08,0) 3(-2.54,0) 5(2.54,0) 6(5.08,0) 7(7.62,0) 8(10.16,0)
  oval 2x8 hole 2 slot 8 at 90 deg unplated: ""(0,0)
  silkscreen extent -9.62,-5.8 12.2,3.31, body extent -9.62,-5.79 12.18,3.32, height 11.2

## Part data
BZ1: "Transducer, 2 V to 5 V, 75 dB, Sounder, 30 mA, Through Hole", Supplier Part Number 1=2534976
C1 C4 C7 C8 C9 C19 C20 C21 C23 C24 C26 C27 C29 C32 C33: library part "CAP NP", "Capacitor  0805", Dielectric=X7R, Manufacturer 1=VISHAY, MPN 1=VJ0805Y104KXACW1BC, Supplier Part Number 1=2407344, Voltage=50V
C2 C3: library part "CAP NP", "Capacitor  0805", Dielectric=NP0, Manufacturer 1=VISHAY, MPN 1=VJ0805A220JXBAC, Supplier Part Number 1=2896722
C5 C11: library part "CAP NP", "Capacitor  0804", Supplier Part Number 1=2407344, Voltage=50V
C6 C22 C25 C28 C30 C31 C34 C35 C36 C37: library part "CAP NP", "Capacitor  0805", Dielectric=X7R, Manufacturer 1=MURATA, MPN 1=GCM21BR70J106KE22L, Supplier Part Number 1=2470434, Voltage=6V3
C10 C14 C15: library part "CAP NP", "Capacitor  0805", Supplier Part Number 1=2407344, Voltage=50V
C12 C13 C16 C17 C18: library part "CAP NP", "Capacitor  0603", Supplier Part Number 1=2407344, Voltage=50V
C38 C39: library part "Capacitor P_2", "Cap Aluminum 47uF 16V 20% (5 X 5.8mm) SMD 0.36 Ohm 240mA 2000 hr 105°C Embossed T/R", Case/Package=SMD/SMT, ESR (Equivalent Series Resistance)=360mR, Leakage Current=7.5uA, Manufacturer 1=Panasonic, Manufacturer Part Number 1=EEE-FPC470UAR, Max Operating Temperature=105°C, Min Operating Temperature=-55°C, Package Quantity=1000, Ratings=AEC-Q200, Ripple Current=240mA, Supplier Part Number 1=2408640, Tolerance=20%, Voltage=16V
D1 D2 D3 D4 D5 D6 D10 D11 D17: library part "Diode ESDALC6V1W5_1", "Quad TRANSIL array for data protection TVS Diodes", Breakdown Voltage=7.2V, Capacitance=7.5pF, Case/Package=SOT-323, Leakage Current=1uA, Manufacturer 1=STMicroelectronics, Max Operating Temperature=150°C, Max Power Dissipation=25W, Min Breakdown Voltage=6.1V, Min Operating Temperature=-55°C, Operating Supply Voltage=3V, Package Quantity=1, Peak Pulse Current=15A, Power Line Protection=No, Resistor Type=Zener, Supplier Part Number 1=497-7231-1-ND, Test Current=1mA
D7 D8 D9 D12 D19 D20: library part "Diode BAT54WFILM", "Schottky Diode", Average Rectified Current=300mA, Capacitance=10pF, Case/Package=SOT-323, Forward Voltage=900mV, Manufacturer 1=STMicroelectronics, Max Forward Surge Current (Ifsm)=1A, Max Operating Temperature=150°C, Max Repetitive Reverse Voltage (Vrrm)=40V, Max Reverse Current=1uA, Min Operating Temperature=-40°C, Package Quantity=1, Supplier Part Number 1=3214563, Voltage Rating (DC)=30V
D18 LED0 LED1 LED2 LED3: library part Component_1
FID1 FID2 FID3 FID4 FID5 FID6: library part CMP-0077181-1, "Fiducial mark.  There is nothing to buy or mount.", Manufacturer=N/A
J1: library part MC34755, "No Description Available", Mfr_Name=Multicomp
J2 P3 P4: library part 826947-6, "No Description Available", Mfr_Name="TE Connectivity"
J3: Package=None
NT1: library part NET-TIE, "NET-TIE"
P1: library part "Header 16X2", "Header, 16-Pin, Dual row"
P2: library part "Header 8X2", "Header, 8-Pin, Dual row"
Q1: library part "NPN 2STR1160", "NPN Bipolar Transistor", Case/Package=SOT-23, Collector Base Voltage (VCBO)=60V, Collector Emitter Saturation Voltage=430mV, Emitter Base Voltage (VEBO)=5V, Manufacturer 1=STMicroelectronics, Max Collector Current=1A, Max Operating Temperature=150°C, Max Power Dissipation=500mW, Min Operating Temperature=-65°C, Package Quantity=1, Supplier Part Number 1=511-2STR1160
R1 R2 R3 R4 R5 R6 R7 R8 R9 R10 R11 R12 R13 R14 R15 R16 R17 R18 R19 R20 R21 R22 R23 R24 R25 R26 R27 R28 R29 R30 R31 R32 R33 R34 R35 R36 R37 R38 R39 R40 R41 R42 R43 R44 R45: library part RESISTOR, "RESISTOR 0805"
SW1: library part "SWITCH TACT NO_2", "Tact Switch Normally Open", MPN 1=SKHHNKA010, Supplier Part Number 1=2056836
SW2: library part "Slide Switch", "Switch Slide ON None ON SPDT Side Slide 0.2A 30VDC 10000Cycle PC Pins Bracket Mount/Through Hole", Manufacturer 1="TE Connectivity AMP", Manufacturer Part Number 1=1825232-1, Supplier Part Number 1=2772069
TP1: library part TESTP, "Test Point", Colour=Black, Supplier Part Number 1=8731195
TP2 TP3 TP4 TP5 TP6 TP7: library part TESTP, "Test Point", Colour=Green, Supplier Part Number 1=8731217
U1: "No Description Available", Mfr_Name=STMicroelectronics
U2 U3: "No Description Available"
U4: library part "Voltage regulator isolated 8P"
U5: library part "Voltage Regulator LDF33DT-TR", "3.3V 1A Very Low Drop Voltage Regulator", Case/Package=TO-252-3, Dropout Voltage=200mV, Manufacturer 1=STMicroelectronics, Max Input Voltage=16V, Max Operating Temperature=125°C, Max Output Current=1A, Min Input Voltage=2.6V, Min Operating Temperature=-40°C, Nominal Output Voltage=3.3V, Operating Supply Current=200uA, Package Quantity=2500, Power Supply Rejection Ratio (PSRR)=60dB, Quiescent Current=800uA, Supplier Part Number 1=2112623
X1: library part "Crystal Resonator 3P", "Crystal, 8Mhz, 18Pf, 5Mm X 3.2Mm Frequency Nom 8Mhz Crystal Case Smd Rohs Compliant: Yes", Manufacturer 1="MULTICOMP PRO", Manufacturer Part Number 1=MCSJK-7I-8.00-18-30-60-B-30, Supplier Part Number 1=2854013

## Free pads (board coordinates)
  round 0.508 on Mech11: 1(79.566,-27.841)
  oval 10x2 hole 2 slot 10 at 0 deg unplated: ""(71.4,73.7) ""(95.24,73.7)
  oval 5x2 hole 2 slot 5 at 0 deg unplated: ""(76.4,73.7)

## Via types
v1: diameter 0.61, hole 0.305, Top Layer to Bottom Layer, tented both sides, 249 vias
v2: diameter 0.6, hole 0.3, Top Layer to Bottom Layer, tented both sides, 45 vias
v3: diameter 0.65, hole 0.3, Top Layer to Bottom Layer, 12 vias
v4: diameter 0.62, hole 0.31, Top Layer to Bottom Layer, 9 vias

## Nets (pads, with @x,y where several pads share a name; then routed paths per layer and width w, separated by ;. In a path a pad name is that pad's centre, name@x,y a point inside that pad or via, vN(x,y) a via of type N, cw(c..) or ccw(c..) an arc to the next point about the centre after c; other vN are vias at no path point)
16V_Enable: P1.16 U1.30 | length 60.5
  Top Layer w0.152: 47.08,2.786 52.366,2.786 P1.16@53.82,4.24
  Top Layer w0.203: U1.30@43.264,47.479 45.029,47.479 45.264,47.245 45.264,45.804 42.617,43.157 42.617,39.986 41.066,38.435 41.066,29.19 42.52,27.737 42.52,3.361 43.094,2.786 47.08,2.786
+3V3: BZ1.1 C4.1 C6.1 C7.1 C8.1 C9.1 C19.1 C21.1 C24.1 C36.1 C37.1 C39.1 D7.3 D18.2 J1.10 J2.1 J3.3 LED0.2 LED1.2 LED2.2 LED3.2 P1.8 R1.1 R11.2 R12.2 R13.1 R14.2 R16.2 R17.2 R21.2 R22.2 R25.2 R28.1 R29.1 R30.2 R31.2 R39.1 TP3.1 U1.16 U1.32 U1.48 U1.64 U2.1 U3.1 U5.3 | length 67.3
  Top Layer w0.2: C21.1@41.5,59.1 41.668,58.932 41.668,58.342 41.866,58.144 ; 42.503,45.656 42.767,45.921 42.767,46.427 42.82,46.479 U1.32@43.264,46.479 43.264,45.981 ; 44.529,55.979 U1.16@45.264,55.979 45.264,56.424 45.212,56.476 45.181,56.476 44.736,56.921 ; 53.264,44.479 U1.48@52.764,44.479 52.776,44.467 52.776,43.718 53.587,43.718
  Top Layer w0.3: TP3.1@21.948,16.053 D18.2@21.948,19.325 ; 54.764,54.422 U1.64@54.764,53.979 55.729,53.979 55.9,54.15
  Top Layer w0.5: R16.2@17.95,65.65 18.1,65.8 D7.3@20.1,65.8 22,65.8 C4.1@22.3,65.5 22.3,67.166 21.1,68.366 BZ1.1@21.1,71.6 ; C24.1@68.06,66.7 68.06,68.065 68.332,68.337 69.466,68.337 69.495,68.366 U3.1@69.495,68.899 ; C8.1@91.9,66.7 91.9,68.065 92.172,68.337 93.306,68.337 93.335,68.366 U2.1@93.335,68.899
  Top Layer w0.508: v1(30.919,50.6) v1@30.933,50.585 ; v1(58.878,62.421) R29.1@58.878,61.221 v1(60.216,61.221)
  Top Layer w0.6: R1.1@43.236,67.986 v1(43.236,69.172) ; v1(67.279,63.6) R31.2@68.65,63.6 ; v1(68.06,65.329) C24.1@68.06,66.7 v1(69.431,66.7) ; v1(73.55,35.679) R14.2@73.55,37.05 ; R30.2@74.15,63.6 v1(75.521,63.6) ; v1(90.05,61.429) R22.2@90.05,62.8 ; R11.2@91.7,18.65 v1(91.7,20.021) ; v1(91.9,65.329) C8.1@91.9,66.7 v1(93.271,66.7) ; R12.2@93.7,18.65 v1(93.7,20.021) ; v1(95.679,22.16) R13.1@97.05,22.16 v1(97.05,23.531) ; v1(98.35,61.429) R21.2@98.35,62.8
  Top Layer w0.762: v1(1.328,43.369) LED3.2@2.894,43.369 v1(2.894,44.535) ; v1(1.328,46.306) LED2.2@2.894,46.306 v1(2.894,47.471) ; v1(1.328,49.242) LED1.2@2.894,49.242 v1(2.894,50.407) ; v1(1.328,52.178) LED0.2@2.894,52.178 v1(2.894,53.343) ; v1(29.636,43.797) R28.1@30.933,43.797 v1(30.933,42.662) ; v1(29.636,49.45) R39.1@30.933,49.45 v1@30.933,50.585
  other v1: 17.252,11.877 19.423,11.877 16.702,13.719 19.423,14.35 19.4,16.689 40.588,40.4 41.8,40.4 41.762,41.689 41.762,42.85 54,43.5 58.534,55.405 58.534,56.855 59.901,56.855 41.866,57.592
  other v2: 18.338,13 20.795,13
+5V: C34.1 C35.1 C38.1 J1.9 P1.6 P2.5 R41.2 TP2.1 U5.1 | length 152.4
  Top Layer w0.6: v1(83.9,55.079) R41.2@83.9,56.45
  Top Layer w1: P1.6@41.12,4.24 41.12,2.542 41.706,1.956 90.274,1.956 96.52,8.202
  Bottom Layer w1: 83.9,56.4 v1(83.9,55.079) 83.9,38.999 91.899,31 96.302,31 102.602,24.7 ; 96.52,8.202 96.52,18.618 102.602,24.7 ; P2.5@104.46,24.7 102.602,24.7
  Bottom Layer w1.5: J1.9@9.95,35.04 12.869,35.04 27.973,19.937 TP2.1@27.973,16.053
  other v1: 95.938,7.62 97.021,7.62 95.938,8.702 97.021,8.702 29.761,11.949 31.941,11.949 29.761,14.553 31.941,14.553 29.761,16.732 31.941,16.732 82.529,55.079 85.271,55.079 82.529,56.45 85.271,56.45
"+5V iso": C27.1 C32.1 C33.1 P4.3 R32.2 R33.2 U3.8 U4.6 | length 13.9
  Top Layer w0.5: C27.1@68.5,80.7 68.5,79.496 68.932,79.063 69.466,79.063 69.495,79.034 U3.8@69.495,78.501
  Top Layer w0.6: v1(65.459,87.15) R32.2@66.83,87.15 ; C27.1@68.5,80.7 C27.1@68.6,80.7 ; v1(68.6,82.071) C27.1@68.6,80.7 ; v1(69.871,80.7) C27.1@68.6,80.7 ; R33.2@73.17,87.15 v1(74.541,87.15) ; v1(76.1,80.274) C32.1@76.1,81.645 v1(77.471,81.645) ; v1(76.1,85.071) C33.1@76.1,83.7 v1(77.471,83.7)
+16V: P1.4 P2.3 | length 89.4
  Power Layer w1: P1.4@38.58,4.24 36.747,2.407 34.336,2.407 33.75,2.992 33.75,7.85 34.85,8.95 86.17,8.95 102.438,25.218 P2.3@104.46,27.24
+24V: P1.2 P2.1 | length 88.5
  Top Layer w1.5: 88.875,20.584 v1(89.375,21.085) 98.071,29.78 P2.1@104.46,29.78
  Bottom Layer w1.5: P1.2@36.04,4.24 36.04,3.456 38.009,1.487 81.293,1.487 88.875,9.068 88.875,20.584
  other v1: 88.293,20.002 89.375,20.002 88.293,21.085
BOOT: R17.1 R18.1 U1.61 | length 7.6
  Top Layer w0.203: U1.61@54.764,52.479 58.351,52.479 R17.1@59.719,53.847 ; R17.1@59.9,53.797 R18.1@61.998,53.797
BUZZER_PWM: R20.2 U1.25 | length 32.2
  Top Layer w0.203: R20.2@25.8,63.35 36.15,63.35 38.5,61 38.5,57.352 39.175,56.677 v4(43.4,56.677) ; U1.25@43.264,49.979 44.566,49.979 v4(44.583,49.962)
  Bottom Layer w0.203: v4(43.4,56.677) 43.4,56.63 42.247,55.477 42.247,54.164 42.609,53.802 42.609,51.544 44.155,49.998 44.547,49.998 v4(44.583,49.962)
COM_Slot: D11.4 P2.14 R3.2 | length 79.8
  Top Layer w0.203: R3.2@45,31.55 45,29.905 45.805,29.1 v1(46.7,29.1) ; v1(61.385,28.735) 65.42,24.7 70.6,24.7 82.55,12.75 100.744,12.75 101.117,12.377 101.117,10.867 101.513,10.471 101.513,10.396 101.587,10.323 102.137,10.323 102.21,10.249 102.21,10.219 102.329,10.1 107.64,10.1 108.7,11.16 108.7,14.11 108.27,14.54 P2.14@107,14.54
  Bottom Layer w0.203: v1(46.7,29.1) 47.065,28.735 v1(61.385,28.735)
DebugRx: D9.3 D19.1 D20.1 R22.1 U1.60 | length 140.3
  Top Layer w0.203: v1(46.055,76.288) 52.524,76.288 67.8,61.012 67.8,57.435 70.835,54.4 74.87,54.4 75.686,53.584 75.686,52.774 ; U1.60@54.764,51.979 58.775,51.979 59.569,52.774 75.686,52.774 ; D9.3@73.55,43.6 v1(73.55,44.7) ; R22.1@91.95,62.8 93.402,62.8 93.55,62.652 D19.1@93.55,62.6 93.55,57.076 88.848,52.374 v1(76.086,52.374) 75.686,52.774
  Top Layer w0.3: D20.1@14.204,89.856 14.204,87.118 v1(15.43,85.891)
  Bottom Layer w0.203: v1(15.43,85.891) 16.339,86.8 23,86.8 33.7,76.1 45.866,76.1 v1(46.055,76.288) ; v1@73.55,44.6 v1@73.6,44.65 ; v1(73.55,44.7) 76.086,47.236 v1(76.086,52.374)
DebugTx: R15.1 R21.1 R44.2 U2.3 | length 126.9
  Top Layer w0.203: v1(46.055,75.412) 52.045,75.412 67,60.457 67,56.857 70.337,53.52 v1(73.937,53.52) ; R15.1@62.156,51.455 73.537,51.455 v1(73.937,51.055) 74.337,51.455 89.593,51.455 96.45,58.312 R21.1@96.45,62.8 ; U2.3@95.875,68.899 95.875,66.359 96.433,65.801 R21.1@96.433,62.8
  Top Layer w0.3: v1(17.43,85.891) R44.2@17.43,90.05
  Bottom Layer w0.203: v1(17.43,85.891) 22.909,85.891 33.2,75.6 45.866,75.6 v1(46.055,75.412) ; v1(73.937,51.055) v1(73.937,53.52)
Fan1_PWM: D3.1 P1.10 U1.40 | length 44.1
  Top Layer w0.203: P1.10@46.2,4.24 45.108,5.332 45.108,9.394 44.416,10.086 44.416,14.283 49.983,19.85 49.983,34.276 50.309,34.602 50.309,41.401 48.764,42.946 U1.40@48.764,44.479
Fan2_PWM: D3.3 P1.12 U1.41 | length 44.2
  Top Layer w0.152: 47.23,8.072 47.255,8.046 47.255,5.582 48.598,4.24 P1.12@48.74,4.24 ; U1.41@49.264,44.479 49.264,43.021 50.578,41.706 50.715,41.569 50.715,35.662 50.741,35.637 50.741,35.341
  Top Layer w0.203: 47.23,8.072 47.23,8.097 46.482,8.845 46.408,8.919 46.408,10.208 45.758,10.858 45.758,14.423 50.415,19.08 50.415,34.098 50.741,34.423 50.741,35.341
FOD_Slot: D10.5 P2.15 R19.2 | length 76.1
  Top Layer w0.203: R19.2@43.1,31.55 43.1,30.148 45.486,27.762 v1(46.594,27.762) ; v1(65.35,27.75) 65.362,27.762 71.873,27.762 72.896,26.739 ; 72.897,26.739 85.096,14.54 99.944,14.54 101.041,15.637 101.041,16.158 101.662,16.779 D10.5@101.862,16.779 102.062,16.779 103.041,15.8 105.2,15.8 105.7,15.3 105.7,13.24 P2.15@104.46,12
  Bottom Layer w0.203: v1(46.594,27.762) 46.6,27.756 65.344,27.756 v1(65.35,27.75)
GND: C1.2 C4.2 C5.2 C6.2 C7.2 C8.2 C9.2 C10.2 C11.2 C12.2 C13.2 C14.2 C15.2 C16.2 C17.2 C18.2 C19.2 C21.2 C22.2 C23.2 C24.2 C25.2 C26.2 C28.2 C29.2 C30.2 C31.2 C34.2 C35.2 C36.2 C37.2 C38.2 C39.2 D1.2 D2.2 D3.2 D4.2 D5.2 D6.2 D10.2 D11.2 D17.2 J1.1 J2.5 J3.5 J3.7 J3.11 NT1.2 P1.1 P1.3 P1.5 P1.7 P1.17 P1.18 P1.29 P1.30 P1.31 P1.32 P2.2 P2.4 P2.6 P2.8 Q1.2 R18.2 R43.2 R45.2 SW1.2 TP4.1 TP5.1 TP6.1 TP7.1 U1.15 U1.27 U1.31 U1.47 U1.63 U2.4 U3.4 U4.1 U5.2 | length 50.2
  Top Layer w0.203: U1.63@54.764,53.479 56.811,53.479 C7.2@57.179,53.847
  Top Layer w0.254: v3(37.106,47.218) 37.538,47.65 C16.2@40.5,47.65 ; U1.31@43.264,46.979 44.344,46.979 44.493,46.83 v4(44.493,46.632) ; U1.27@43.264,48.979 v3(44.508,48.979)
  Top Layer w0.3: R43.2@9.95,12.237 J1.1@9.95,14.72 ; v1(24,18.4) R45.2@24,19.55 ; C15.2@38.5,52.9 40.45,52.9 C11.2@40.5,52.85 ; v1(40.102,60.9) C21.2@41.5,60.9 ; v1(44.683,77) 44.683,82.268 SW1.2@46.565,84.15 ; U1.15@45.764,55.979 45.764,54.806 v4(45.795,54.775) ; U1.47@52.264,44.479 52.264,43.492 52.5,43.256 52.5,43 ; C5.2@52.3,61.15 52.35,61.1 v2(53.4,61.1)
  Top Layer w0.305: v1(24.05,89.5) 24.05,89.582 24.4,89.932 D17.2@24.4,90.842 ; v1(45.467,10.177) 45.758,9.885 D3.2@45.758,9.194 ; v1(58.25,10.3) 58.542,10.008 D5.2@58.542,9.316 ; D6.2@64.742,10.97 v1(64.742,12.053) ; v1@98.681,16.129 D10.2@99.662,16.129
  Top Layer w0.35: v1(11.474,23.518) D1.2@12.533,23.518 ; v1(11.7,33.174) 11.71,33.164 D2.2@12.533,33.164 ; v1(98.679,10.973) D11.2@99.662,10.973
  Top Layer w0.381: v1(32.857,42.647) C22.2@32.857,43.847 ; C28.2@32.857,49.4 v1(32.857,50.391) ; v1(35.107,42.662) C23.2@35.107,43.862 ; v1(35.107,50.6) C29.2@35.107,49.4 C29.2@35.498,49.01 ; D4.2@52.371,11.415 52.371,11.871 v1(52.4,11.9) ; v1(98.679,16.127) v1@98.681,16.129
  Top Layer w0.508: C26.2@54.666,61.171 55.314,61.819 v1(55.314,62.413) ; C25.2@56.808,61.171 v1(56.808,62.371) ; C7.2@57.179,53.847 v1(58.394,53.847) ; v1(61.932,56.874) v1@61.952,56.854 ; R18.2@61.952,55.744 R18.2@61.998,55.697 R18.2@62.004,55.704
  Top Layer w0.635: C6.2@38.114,42.494 C6.2@38.14,42.52 ; C1.2@48.8,61.063 C1.2@48.916,60.946
  Top Layer w0.762: R18.2@61.952,55.744 v1@61.952,56.854
  Bottom Layer w0.254: 45.873,40.423 45.9,40.45
  Bottom Layer w0.381: v1(48.035,49.234) 48.035,50.355 ; 49.459,46.555 49.744,46.84 49.744,47.278 50.054,47.588 50.373,47.588 v1(50.416,47.632)
  other v1: 29.761,2 31.941,2 29.761,4.99 31.941,4.99 17.252,7.335 19.423,7.335 29.761,7.53 31.941,7.53 15.881,8.706 20.795,8.706 75.046,12.05 77.1,12.05 67.513,13.839 48.339,13.9 67.513,16.231 50.28,16.272 32.5,18.942 18.3,19.133 32.5,20.934 18.3,21.125 45.15,21.4 40.2,21.796 52.746,26.948 40.559,27.751 66.6,29.5 59.9,31.95 53.135,40.086 38.067,40.8 58.819,41.38 47.717,48.346 51.613,48.717 50.19,49.225 50.196,51.016 53.142,53.832 64.2,56 53.81,57.089 39.863,57.498 54.764,57.928 82.1,58.863 80.729,60.234 47.6,61.5 80.729,62.384 24.1,62.5 22.95,63.35 82.1,63.755 24.1,64.2 44.7,65.113 55.7,65.313 66.26,65.329 90.1,65.329 64.889,66.7 88.729,66.7 97.145,67.283 66.26,68.071 90.1,68.071 98.25,68.884 44.815,69.172 55.7,69.172
  other v2: 20.549,6.734 81.509,6.734 89.129,6.734 70.079,14.354 5.309,21.974 12.929,21.974 20.549,21.974 28.169,21.974 35.789,21.974 58.649,21.974 31.979,29.594 70.079,29.594 77.699,29.594 85.319,29.594 5.309,37.214 20.549,37.214 28.169,37.214 35.789,37.214 58.649,37.214 81.509,37.214 89.129,37.214 96.749,37.214 9.119,44.834 77.699,44.834 85.319,44.834 92.939,44.834 100.559,44.834 108.179,44.834 96.749,52.454 16.739,60.074 85.319,60.074 5.309,67.694 28.169,67.694 104.369,67.694 16.739,75.314 24.359,75.314 54.839,75.314 5.309,82.934 28.169,82.934 9.119,90.554
  other v3: 40.326,37.214 44.92,37.5 46.4,37.5 48.516,37.5 37.045,42.3 37.045,44.5 44.05,62.052
Gnd1: C2.1 C3.2 NT1.1 X1.2 | length 10.4
  Top Layer w0.203: v1(53.315,64.821) 53.325,64.81 C3.2@53.325,63.554
  Top Layer w0.635: v1(47.1,67.857) v1(47.1,68.7) 48.635,68.7 X1.2@48.675,68.66 ; C2.1@47.794,63.554 47.798,63.559 v1(47.798,64.821) v1(48.641,64.821) ; X1.2@52.375,66.46 52.435,66.4 v1(54,66.4) v1(54,65.557) ; v1(52.472,64.821) v1(53.315,64.821) 53.315,63.565 C3.2@53.325,63.554
"GND iso": C27.2 C32.2 C33.2 P4.1 U3.5 U4.7 | length 5.5
  Top Layer w0.6: v1(72.929,81.645) C32.2@74.3,81.645 v1(74.3,80.274) ; v1(72.929,83.7) C33.2@74.3,83.7 v1(74.3,85.071)
  other v1: 74.12,78.532 66.7,79.329 66.7,82.071 63.984,85.2 61.11,87.15 79,87.15 77,90.4
GPIO2: D1.5 J1.3 U1.18 | length 57.8
  Top Layer w0.203: J1.3@9.95,19.8 12.041,19.8 13.913,21.672 13.913,23.622 14.458,24.168 14.985,24.168 15.058,24.241 15.058,25.994 19,29.935 19,43.5 29.5,54 41,54 41.521,53.479 U1.18@43.264,53.479
GPIO3: D1.3 J1.4 U1.17 | length 55.9
  Top Layer w0.203: J1.4@9.95,22.34 11.731,22.34 12.258,22.868 13.174,22.868 13.4,23.094 13.4,25.9 18,30.5 18,43.111 29.389,54.5 41.111,54.5 41.631,53.979 U1.17@43.264,53.979
GPIO4: D1.1 J1.5 U1.3 | length 73.7
  Top Layer w0.203: J1.5@9.95,24.88 10.039,24.791 11.136,24.791 11.759,24.168 D1.1@12.533,24.168 12.533,26.575 16.949,30.991 16.949,43.249 28.2,54.5 v1(28.3,54.5) ; v1(51.359,54.127) 51.764,54.533 U1.3@51.764,55.979
  Bottom Layer w0.203: v1(28.3,54.5) 28.366,54.434 34.76,54.434 41.496,61.17 46.628,61.17 47.298,60.5 48.6,60.5 49.101,59.999 49.101,54.812 49.786,54.127 v1(51.359,54.127)
GPIO5: D2.4 J1.6 U1.23 | length 58
  Top Layer w0.203: J1.6@9.95,27.42 11.64,27.42 14.534,30.313 14.534,32.514 15.286,32.514 15.793,33.021 15.793,43.045 27.948,55.2 42,55.2 42.425,54.775 43.068,54.775 v4(43.1,54.742) ; U1.23@43.264,50.979 44.583,50.979 v4(44.591,50.987)
  Bottom Layer w0.203: v4(43.1,54.742) 43.1,52.053 44.147,51.007 44.572,51.007 v4(44.591,50.987)
GPIO6: D2.3 J1.7 U1.10 | length 57.7
  Top Layer w0.203: J1.7@9.95,29.96 11.302,29.96 12.533,31.191 D2.3@12.533,32.514 13.225,32.514 13.633,32.922 13.633,41.833 27.432,55.632 42.178,55.632 42.428,55.382 43.449,55.382 45.212,53.619 47.48,53.619 48.264,54.403 48.264,55.878 48.213,55.928 U1.10@48.264,55.979
GPIO7: D2.1 J1.8 U1.11 | length 54.7
  Top Layer w0.203: J1.8@9.95,32.5 10.05,32.5 11.364,33.814 D2.1@12.533,33.814 12.808,33.814 12.881,33.888 12.881,41.785 27.16,56.064 42.357,56.064 42.543,55.878 43.787,55.878 45.613,54.051 47.301,54.051 47.764,54.514 U1.11@47.764,55.979
Heatsink_Temp_p: C15.1 D5.4 P1.21 U1.20 | length 60.7
  Top Layer w0.203: C15.1@38.787,51.5 38.861,51.573 38.861,51.861 39,52 41.217,52 41.696,52.479 v3(41.954,52.479) U1.20@43.264,52.479 ; v1(58.039,15.113) 59.192,13.96 D5.4@59.192,11.516 59.192,11.316 59.34,11.168 61.44,9.068 P1.21@61.44,6.78
  Bottom Layer w0.203: v3(41.954,52.479) 41.954,51.093 43.768,49.278 43.768,26.203 54.858,15.113 v1(58.039,15.113)
IACn: C13.1 P1.28 U1.14 | length 80.3
  Top Layer w0.203: C13.1@44,59.15 44.05,59.15 44.498,58.702 44.498,58.652 45.76,57.39 v2(45.795,57.39) 46.264,56.921 U1.14@46.264,55.979 ; v1(67.818,10.65) 67.818,5.482 P1.28@69.06,4.24
  Bottom Layer w0.203: v2(45.795,57.39) 43.207,57.39 39.337,53.52 39.337,28.076 43.325,24.088 44.812,24.088 54.55,14.35 64.118,14.35 v1(67.818,10.65)
IACp: C18.1 P1.27 U1.13 U1.42 | length 70.4
  Top Layer w0.203: C18.1@46.5,59.15 46.55,59.15 46.998,58.702 46.998,58.652 47.432,58.218 47.432,57.701 ; U1.13@46.764,55.979 46.764,57.033 47.432,57.701 ; v3(48.399,57.701) v3(48.399,57.701) 47.432,57.701 ; U1.42@49.764,44.479 49.815,44.53 49.815,45.576 50.233,45.995 v1(50.764,45.995) ; P1.27@69.06,6.78 v1(69.06,21.076)
  Bottom Layer w0.203: v3(48.399,57.701) 48.4,54.902 53.619,49.682 53.619,48.85 v1(50.764,45.995) 50.764,45.225 51.219,44.77 53.73,44.77 69.06,29.44 v1(69.06,21.076)
IDCn: C12.1 D6.1 P1.26 U1.37 | length 55.8
  Top Layer w0.203: U1.37@47.264,44.479 47.264,42.396 48.5,41.16 C12.1@48.5,40.35 48.45,40.35 48.002,39.902 48.002,39.852 47.583,39.432 47.583,34.839 47,34.256 47,30.309 47.93,29.379 47.93,26.694 v1(47.97,26.654) ; v1(65.345,15.5) 65.377,15.468 65.377,10.986 D6.1@65.392,10.97 65.392,10.02 64.795,9.423 64.795,7.798 65.278,7.315 65.278,5.482 P1.26@66.52,4.24
  Bottom Layer w0.203: v1(47.97,26.654) 47.97,26.614 57.091,17.493 65.539,17.493 66.091,16.941 66.091,15.759 65.832,15.5 v1(65.345,15.5)
IDCp: C17.1 D6.5 P1.25 U1.36 | length 61.8
  Top Layer w0.203: C17.1@46.998,39.852 46.998,39.902 46.55,40.35 C17.1@46.5,40.35 46.5,43.273 46.764,43.537 U1.36@46.764,44.479 46.764,45.316 47.1,45.652 v1(48.416,45.652) ; v1(65.293,16.561) 66.027,15.827 66.027,9.605 65.392,8.97 D6.5@65.392,8.77 65.392,7.908 66.421,6.88 66.421,6.78 P1.25@66.52,6.78
  Bottom Layer w0.203: v1(48.416,45.652) 47.861,45.096 47.861,36.666 45.745,34.55 45.745,27.443 55.468,17.721 56.628,16.561 v1(65.293,16.561)
IGBT_drive: D11.5 P2.16 R4.2 | length 69.2
  Top Layer w0.203: v1(61.385,30.286) 66.071,25.6 71.212,25.6 83.512,13.3 100.963,13.3 101.862,12.402 D11.5@101.862,11.623 102.582,11.623 103.605,10.6 105.6,10.6 P2.16@107,12
  Top Layer w0.254: v1(48.342,30.163) R4.2@48.342,31.507
  Bottom Layer w0.203: v1(48.342,30.163) 48.42,30.241 48.62,30.241 48.664,30.286 v1(61.385,30.286)
Led0: R34.2 U1.46 | length 91.2
  Top Layer w0.203: R34.2@9.009,52.178 17.028,52.178 24.55,59.7 v1(37.1,59.7) ; U1.46@51.764,44.479 v1(51.764,46.01)
  Bottom Layer w0.203: v1(37.1,59.7) 37.046,59.754 37.046,66.509 42.537,72 55.368,72 59.6,67.768 59.6,61.7 54.712,56.812 54.712,48.958 v1(51.764,46.01)
Led1: R35.2 U1.51 | length 94.3
  Top Layer w0.203: R35.2@9.009,49.242 15.622,49.242 25.03,58.65 v1(36.05,58.65) ; U1.51@54.764,47.479 56.689,47.479 56.824,47.344 v1(56.934,47.344)
  Bottom Layer w0.203: v1(36.05,58.65) 36.05,66.732 41.818,72.5 55.7,72.5 60.9,67.3 60.9,60.6 59.9,59.6 58.943,59.6 55.143,55.801 55.143,49.135 v1(56.934,47.344)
